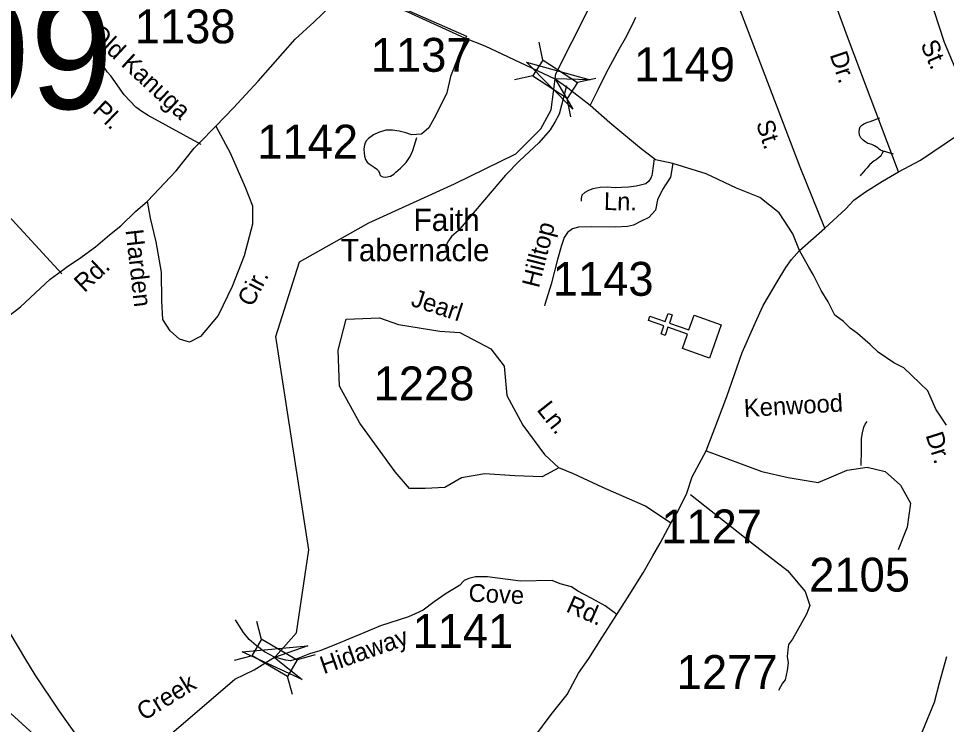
# Model space of a CAD drawing. Extents: x 884530 to 1028605, y 526725 to 653634.
# Drawn here: x 959170 to 962593, y 575826 to 578430 of the extents above; entities that cross this region are included whole.
import ezdxf

# ---------------------------------------------------------------- set-up
doc = ezdxf.new("R2010")
doc.units = 0
for name, color, linetype in [('Exist Cultural Church CELL', 7, 'Continuous'), ('Exist Cultural Church Label', 7, 'Continuous'), ('Exist Hydrographic Creek Single Shore', 7, 'Continuous'), ('Exist Hydrographic Creek Single Shore Label', 7, 'Continuous'), ('Exist Road Non-System Type 51', 7, 'Continuous'), ('Exist Road Non-System Type 51 Label', 7, 'Continuous'), ('Exist Road Secondary Structure Standard Bridge Attributed CELL', 7, 'Continuous'), ('Exist Road Secondary Structure Standard Bridge CELL', 7, 'Continuous'), ('Exist Road Secondary Structure Standard Bridge Number Label', 7, 'Continuous'), ('Exist Road Secondary Type 10 Attributed', 7, 'Continuous'), ('Exist Road Secondary Type 41 Attributed', 7, 'Continuous'), ('Exist Road Secondary Type 51 Attributed', 7, 'Continuous'), ('Exist Road Secondary Type 51 Label', 7, 'Continuous'), ('Exist Road Secondary Type 51 Number Label', 7, 'Continuous')]:
    doc.layers.add(name, color=color, linetype=linetype)

msp = doc.modelspace()

# ---------------------------------------------------------------- linework, layer by layer
at = {"layer": 'Exist Cultural Church CELL'}
msp.add_lwpolyline([(961619.3, 577212.5), (961638, 577266.2), (961566.1, 577291.4), (961555.5, 577261.2), (961540.4, 577266.4), (961551, 577296.6), (961494.2, 577316.5), (961499.5, 577331.6), (961556.3, 577311.8), (961566.8, 577342), (961581.9, 577336.7), (961571.4, 577306.5), (961643.2, 577281.4), (961662.4, 577335.7), (961762.9, 577300.6), (961719.8, 577177.3)], close=True, dxfattribs=at)
at = {"layer": 'Exist Hydrographic Creek Single Shore'}
msp.add_lwpolyline([(958977.5, 576015.4), (959293, 575728.8), (959335.2, 575685.1), (959413.1, 575618.2), (959585.1, 575674.8), (959717.4, 575777.9), (959967.7, 575992.9), (960039.8, 576027), (960118.1, 576076.5), (960196.1, 576164.2), (960240.7, 576470.6), (960162.2, 576977.9), (960119.3, 577256.6), (960207, 577531.8), (960463.2, 577676.8), (960778.6, 577819.5), (961004.4, 577931.2), (961096.6, 578023.4), (961134.8, 578093.1), (961152.8, 578225.7), (961272.9, 578464.9)], dxfattribs=at)
at = {"layer": 'Exist Road Non-System Type 51'}
msp.add_line((960395.8, 578553.7), (960822.7, 578364.1), dxfattribs=at)
for points in [[(960822.7, 578364.1), (960764.2, 578215.5), (960750.3, 578156.2), (960709.6, 578073.6), (960683.4, 578026.3), (960657, 578003.1), (960638.8, 578001.9), (960621.6, 578000.9), (960598.5, 578007.9), (960574.3, 578014), (960550.1, 578018.4), (960525.8, 578018), (960498.6, 578010), (960479.6, 578001.3), (960461.6, 577987.6), (960454.1, 577980.1), (960448.8, 577971.8), (960444.9, 577958.1), (960443.6, 577946.7), (960446.6, 577921.6), (960450.2, 577909.9), (960456.3, 577900.5), (960463.7, 577893.4), (960482.2, 577882), (960491.3, 577875.4), (960497.7, 577868.4), (960501.6, 577858.9), (960503.4, 577852.7), (960508.2, 577848.1), (960514.3, 577846.3), (960524.1, 577844.4), (960543, 577848.6), (960554.4, 577855.2), (960562.8, 577862.7), (960579.5, 577878), (960600.6, 577898.2), (960614.7, 577920.7), (960625.2, 577943.2), (960640.1, 577990.9)], [(959843.8, 577965.1), (959649.1, 578071.5), (959624.8, 578086.7), (959603.1, 578103), (959560, 578148), (959511.3, 578218.3), (959497.8, 578232.7), (959488.7, 578246.3)], [(961191.5, 578181.9), (961164.2, 578077.2), (961149.2, 578047.5), (961131.9, 578019), (961089.7, 577971.7), (961018, 577904.4), (960966.3, 577851.9), (960888.8, 577761.6), (960793, 577647.7), (960768.1, 577625.3), (960756.9, 577610.4), (960748.2, 577594.2), (960747, 577580.6), (960753.2, 577568.2)], [(962360.3, 577939.7), (962355.7, 577941.6), (962350.5, 577944.4), (962345.6, 577947.8), (962339.7, 577952.8), (962328.5, 577960.3), (962318.4, 577964.9), (962310.1, 577967.2), (962303.5, 577969.3), (962295.4, 577973.9), (962286.6, 577980.8), (962278.1, 577989.6), (962273.1, 577999.3), (962270.8, 578011.9), (962272.7, 578022.5), (962275.7, 578029.7), (962280.6, 578035.6), (962288.9, 578041.5), (962297.6, 578045.5), (962303.9, 578046.9), (962312.3, 578050.5), (962347.8, 578064)], [(962360.3, 577939.7), (962355.5, 577931.2), (962352.3, 577926), (962349, 577921.3), (962342.1, 577914.5), (962333.8, 577908.7), (962327, 577905), (962319.2, 577899.3), (962310, 577889.7), (962300.5, 577878.8), (962293.8, 577871.1), (962287.8, 577864.2), (962281.3, 577856.9), (962277.6, 577852.8), (962274.9, 577849.8)], [(962398.5, 577929.8), (962373.3, 577937.1), (962365.7, 577938.8), (962360.3, 577939.7)], [(961515, 577912.4), (961507.6, 577857.7), (961506.4, 577850.3), (961502.9, 577840.8), (961493.8, 577828.6), (961484.7, 577820.5), (961465.3, 577814.6), (961448.7, 577810.9), (961420.4, 577807.3), (961395.2, 577806.3), (961371.4, 577805.8), (961342.4, 577807.8), (961316.3, 577806.8), (961289, 577801.2), (961272.5, 577795.8), (961259.8, 577788.4), (961248.5, 577777.8), (961245.9, 577766.4), (961246.4, 577756.2)], [(959330.6, 577487.8), (959018.5, 577824.8)], [(962279.3, 576780.9), (962280.1, 576838), (962280.4, 576881.1), (962283.4, 576901.9), (962288.9, 576923.1), (962294, 576933.8), (962300.6, 576942.9)], [(961649.2, 576674.4), (961877.7, 576493.6), (962006.8, 576393.5), (962072.1, 576316.6), (962090, 576265.3), (962083.5, 576248.9), (962076.8, 576232.4), (962025.7, 576140.7), (962011, 576121.1), (962007.8, 576101.6), (962006.2, 576077.2), (962009.3, 576052.8), (962006.2, 576025.1), (961998.5, 575991.2), (961988.6, 575978.2), (961973.6, 575951.8)]]:
    msp.add_lwpolyline(points, dxfattribs=at)
at = {"layer": 'Exist Road Secondary Structure Standard Bridge Attributed CELL'}
for points in [[(961215.5, 578095.1), (961044.5, 578268.9), (961279.5, 578203.9), (961149.6, 578207.1)], [(960216.1, 575991.4), (959994.8, 576093.8), (960237.7, 576115.7), (960115, 576073)]]:
    msp.add_lwpolyline(points, close=True, dxfattribs=at)
at = {"layer": 'Exist Road Secondary Structure Standard Bridge CELL'}
for p, q in [((961105, 578275.6), (961090.7, 578343.1)), ((961067.4, 578217.8), (960999.9, 578203.4)), ((961299.9, 578208.7), (961232.4, 578194.4)), ((961208.3, 578067.7), (961194, 578135.2)), ((960066.9, 576139.1), (960049, 576205.8)), ((960032.4, 576079.4), (959965.7, 576061.5)), ((960265, 576082.5), (960198.4, 576064.7)), ((960180.9, 575936.9), (960163.1, 576003.5))]:
    msp.add_line(p, q, dxfattribs=at)
for points in [[(961194, 578135.2), (961067.3, 578217.5), (961105.7, 578276.7), (961232.4, 578194.4)], [(960163.1, 576003.5), (960032.2, 576079.1), (960067.5, 576140.2), (960198.4, 576064.7)]]:
    msp.add_lwpolyline(points, close=True, dxfattribs=at)
at = {"layer": 'Exist Road Secondary Type 10 Attributed'}
msp.add_lwpolyline([(961583.8, 577895), (961575.8, 577844.2), (961546.4, 577798.7), (961527.7, 577761.3), (961520.5, 577723.1), (961495.6, 577695.8), (961465.1, 577681), (961438.6, 577667.9), (961416.5, 577662.6), (961374.2, 577660), (961282.4, 577661.3), (961236.2, 577660.8), (961214.1, 577653.6), (961195.6, 577640.2), (961182.8, 577622.7), (961171.8, 577589.1), (961158.2, 577541.5), (961134.9, 577450.2), (961112.2, 577375), (961110.9, 577370.2)], dxfattribs=at)
at = {"layer": 'Exist Road Secondary Type 41 Attributed'}
for points in [[(962028.1, 578909.6), (962092.4, 578928.9), (962134.9, 578943.5), (962173.7, 578959.9), (962202.8, 578959.9), (962243.4, 578950.1), (962271.4, 578947.2), (962299.5, 578936.3), (962338.9, 578914.9), (962369.9, 578883.1), (962405.7, 578794), (962455.9, 578694.6), (962492.8, 578607.7), (962547.1, 578459.8), (962584.6, 578342.2), (962634.5, 578226.3), (962651.4, 578168.5), (962707.9, 578044.6)], [(961279.2, 578108.9), (961308.7, 578167.8), (961339, 578230.8), (961385.7, 578316.6), (961409.2, 578357.8), (961436.3, 578410.8), (961447.1, 578434.6)], [(962593.8, 576930.1), (962554.3, 576989.5), (962524.2, 577056.7), (962436.5, 577140.9), (962399.1, 577160.2), (962341.7, 577199.7), (962311.7, 577228.1), (962265.1, 577267.8), (962238.3, 577287.9), (962213.2, 577312.8), (962181.3, 577335.8), (962156.9, 577384.7), (962131.6, 577427), (962101.8, 577486), (962085.8, 577513), (962051.4, 577573.7)], [(958738.2, 576941.3), (958821.6, 576829.3), (958878.5, 576721.1), (958913.5, 576641.1), (958928.5, 576610.4), (958973.2, 576497.3), (959020.7, 576394), (959061.8, 576308.5), (959092.9, 576252.5), (959137.7, 576162.9), (959195.9, 576066.1), (959230, 576009), (959320.6, 575875.3), (959410.2, 575748.3), (959428.9, 575696), (959441.5, 575665.4), (959449, 575627.3)], [(961377.9, 576231.8), (961334.1, 576263.2), (961285, 576291), (961234.1, 576318.2), (961210.1, 576333.6), (961168.5, 576345.1), (961139.1, 576357.1), (961022.6, 576354.2), (960900.3, 576370), (960855.7, 576370), (960832, 576364.1), (960813.9, 576356.6), (960796.7, 576338.3), (960747.7, 576309.6), (960703.3, 576278.5), (960662.9, 576247.6), (960633.7, 576233.9), (960608.6, 576222.7), (960505.6, 576189.3), (960444.3, 576164.2), (960393.6, 576143), (960340.5, 576121.2), (960282, 576098.1), (960243.8, 576086.2), (960194.8, 576067.2), (960174.1, 576061.1), (960156, 576063.2), (960115, 576073.7)], [(960115, 576073.7), (960077.4, 576094.5), (960046.4, 576117), (960021.4, 576139.3), (960000.8, 576164.9), (959982.9, 576191.8), (959970.9, 576211.6)], [(962394.4, 575531.5), (962549.4, 575908.1), (962567.8, 575979.3), (962595.2, 576076.6)]]:
    msp.add_lwpolyline(points, dxfattribs=at)
at = {"layer": 'Exist Road Secondary Type 51 Attributed'}
msp.add_line((962051.4, 577573.7), (962144.7, 577656.5), dxfattribs=at)
for points in [[(962144.7, 577656.5), (962053.8, 577881.1), (961820.8, 578489.6), (961653.2, 578937.8), (961544, 579222.1), (961547.6, 579273.1), (961598.6, 579324.1), (961686, 579375.1), (961824.4, 579429.8)], [(962416.8, 577864.1), (962232.1, 578352), (962028.1, 578909.6)], [(959898.1, 578032.9), (959962.8, 578099.8), (960053.8, 578198.5), (960190.4, 578353.3), (960260.9, 578417), (960348.2, 578502.9), (960391.7, 578552.9)], [(961150.1, 578206.1), (960891.3, 578328), (960816.4, 578357.9), (960391.7, 578552.9)], [(961279.2, 578108.9), (961196.1, 578173), (961150.1, 578206.1)], [(961583.8, 577895), (961519.7, 577908.3), (961460.9, 577953.8), (961351.4, 578044.7), (961279.2, 578108.9)], [(959646, 577756.3), (959752.2, 577868.2), (959818.6, 577951.8), (959835.7, 577968.8), (959898.1, 578032.9)], [(959898.1, 578032.9), (959951.4, 577934.7), (960006.4, 577807.5), (960033, 577739.2), (960033, 577670.9), (960002.6, 577555.1), (959959, 577441.2), (959907.1, 577333.9)], [(962416.8, 577864.1), (962497.2, 577907.6), (962637.9, 578002.3), (962689, 578034.7), (962707.9, 578044.6)], [(962051.4, 577573.7), (962027.3, 577635.6), (961976.6, 577713.1), (961904.4, 577769.3), (961818.9, 577804.1), (961706.7, 577857.5), (961583.8, 577895)], [(962144.7, 577656.5), (962222.8, 577728.3), (962251.3, 577759.6), (962294.4, 577790.2), (962357.8, 577829.9), (962416.8, 577864.1)], [(958738.2, 576941.3), (958800.8, 577011.5), (958907, 577134.8), (958988.5, 577208.9), (959058.7, 577269.6), (959128.9, 577328.4), (959177.9, 577366.3), (959287.1, 577468), (959340.6, 577508.1), (959348.9, 577513.8), (959391.9, 577541.8), (959454.9, 577587.3), (959506.4, 577631.7), (959547.4, 577665.2), (959602.4, 577718.3), (959646, 577756.3)], [(959907.1, 577333.9), (959841.4, 577257.1), (959801.6, 577236.2), (959763.6, 577247.6), (959729.5, 577278), (959702.9, 577319.7), (959699.1, 577388.1), (959697.2, 577494.3), (959678.3, 577606.3), (959657.4, 577693.6), (959646, 577756.3)], [(961707, 576835.7), (961748.6, 576944.5), (961783.8, 577035.2), (961839.5, 577197.4), (961887.3, 577305.8), (961917.6, 577370.8), (961968.6, 577459.2), (962000.5, 577512), (962021.7, 577540.8), (962051.4, 577573.7)], [(961163.6, 576772.1), (961102.4, 576739.7), (961001.7, 576743.3), (960890.2, 576750.5), (960803.9, 576736.1), (960742.7, 576700.1), (960670.8, 576696.5), (960613.2, 576696.5), (960559.3, 576757.7), (960429.8, 576937.7), (960354.2, 577073.4), (960349.3, 577206.9), (960378.9, 577320.6)], [(960378.9, 577320.6), (960502.5, 577325.6), (960571.6, 577300.8), (960724.8, 577276.1), (960798.9, 577271.2), (960912.6, 577211.8), (960962, 577147.6), (960971.9, 577038.8), (961031.2, 576930), (961110.2, 576821.2), (961163.6, 576772.1)], [(961576.1, 576568.3), (961602, 576611), (961635.1, 576678.8), (961655.2, 576739.9), (961707, 576835.7)], [(961707, 576835.7), (961912.4, 576758.9), (962010.1, 576737.5), (962119.7, 576718.4), (962226.8, 576763.7), (962300.7, 576775.6), (962367.4, 576758.9), (962424.5, 576708.9), (962460.3, 576642.2), (962448.4, 576554), (962415, 576470.6)], [(961576.1, 576568.3), (961483.7, 576631.7), (961325.4, 576700.1), (961217.5, 576750.5), (961163.6, 576772.1)], [(961377.9, 576231.8), (961416.7, 576293.1), (961474.2, 576385.2), (961510.2, 576448.6), (961537.5, 576494.7), (961576.1, 576568.3)], [(960907.4, 575597.2), (960980.9, 575670.7), (961003, 575691.8), (961040.9, 575733.1), (961074.5, 575781.8), (961134.9, 575862.4), (961193.7, 575936), (961236.5, 576015.5), (961273.8, 576068.9), (961322.6, 576145.9), (961377.9, 576231.8)]]:
    msp.add_lwpolyline(points, dxfattribs=at)

# ---------------------------------------------------------------- texts
at = {"layer": 'Exist Cultural Church Label'}
for s, p in [('Faith', (960627.6, 577646.3)), ('Tabernacle', (960359, 577534.7))]:
    msp.add_text(s, height=82.02, dxfattribs=at).set_placement(p)
at = {"layer": 'Exist Hydrographic Creek Single Shore Label'}
msp.add_text('Creek', height=65.62, rotation=31.8766, dxfattribs=at).set_placement((959632.8, 575837.8))
msp.add_text('Creek', height=65.62, rotation=31.8766, dxfattribs=at).set_placement((959632.8, 575837.8))
at = {"layer": 'Exist Road Non-System Type 51 Label'}
for s, rotation, p in [('Old Kanuga', 317.3654, (959426.9, 578366.7)), ('Pl.', 316.117, (959440.1, 578086.6))]:
    msp.add_text(s, height=65.62, rotation=rotation, dxfattribs=at).set_placement(p)
at = {"layer": 'Exist Road Secondary Structure Standard Bridge Number Label'}
msp.add_text('99', height=410.1, dxfattribs=at).set_placement((958908.7, 578096.1))
at = {"layer": 'Exist Road Secondary Type 51 Label'}
for s, rotation, p in [('St.', 293.2975, (962496.4, 578334.6)), ('Dr.', 288.3487, (962162.2, 578296.4)), ('St.', 288.3487, (961890, 578043.7)), ('Ln.', 359.2209, (961329.5, 577723.4)), ('Harden', 276.4656, (959565, 577649.2)), ('Hilltop', 75.7254, (961089.8, 577433.1)), ('Rd.', 43.1008, (959413.1, 577416.6)), ('Cir.', 62.3833, (960032.4, 577362.7)), ('Jearl', 341.8735, (960614, 577371.3)), ('Kenwood', 3.2228, (961847.8, 576959.9)), ('Ln.', 308.3486, (961079.7, 576986.3)), ('Dr.', 287.5122, (962515.8, 576893.4)), ('Cove', 357.1976, (960829.3, 576279.7)), ('Rd.', 336.1774, (961186.4, 576244.1)), ('Hidaway', 19.4482, (960296.3, 576010.9))]:
    msp.add_text(s, height=65.62, rotation=rotation, dxfattribs=at).set_placement(p)
at = {"layer": 'Exist Road Secondary Type 51 Number Label'}
for s, p in [('1138', (959599, 578338.2)), ('1137', (960469.7, 578233.3)), ('1149', (961441.2, 578198)), ('1142', (960051, 577913.2)), ('1143', (961141.1, 577407.1)), ('1228', (960480.3, 577021.4)), ('1127', (961541.2, 576493.8)), ('2105', (962087.1, 576316.3)), ('1141', (960623.8, 576108.1)), ('1277', (961598.3, 575957))]:
    msp.add_text(s, height=125, dxfattribs=at).set_placement(p)

doc.saveas('drawing.dxf')
